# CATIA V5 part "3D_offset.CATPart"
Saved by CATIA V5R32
Part number: Part1
Bounding box of the stored display mesh (mm): x -119.212 to 139.075, y -20 to 0.001, z -1.314 to 92.725
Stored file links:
  D:\PROJECTS\Project 2022\CATIA V5 6R 2022\Resources\Part Files\c17_catia_v6_6r2022_prt\3D_offset.CATPart
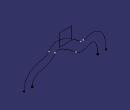
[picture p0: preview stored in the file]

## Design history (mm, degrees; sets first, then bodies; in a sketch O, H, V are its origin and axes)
Set1
  Plane1: type Offset, RefPlane zx-plane, Offset 20, reversed
  Plane2: type Offset, RefPlane Plane1, Offset 20, reversed
  Sketch1 on zx-plane, origin (0, 0, 0), H (-1, 0, 0), V (0, 0, 1)
    spline S1 through (91.2267, 2.5149) (66.4023, 45.9575) (45.4198, 38.8648) (17.3446, 45.9575)
  Sketch2 on Plane1, origin (0, -20, 0), H (-1, 0, 0), V (0, 0, 1)
    spline S1 through (-32.364, 58.2527) (-70.3912, 34.0536) (-101.7704, 22.6188) (-111.0777, -1.3144)
  Connect1: Curve1 Sketch2, Point1 vertex of Sketch2, Tension1 1, Curve2 Sketch1, Point2 vertex of Sketch1, Tension2 1
  Join1: Elements (Connect1; Sketch1; Sketch2)
  3DCurveOffset1: Curve Join1, Direction Plane2, Offset -28, CornerRadius 10, CornerTension 0.5
Body1 (main body)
